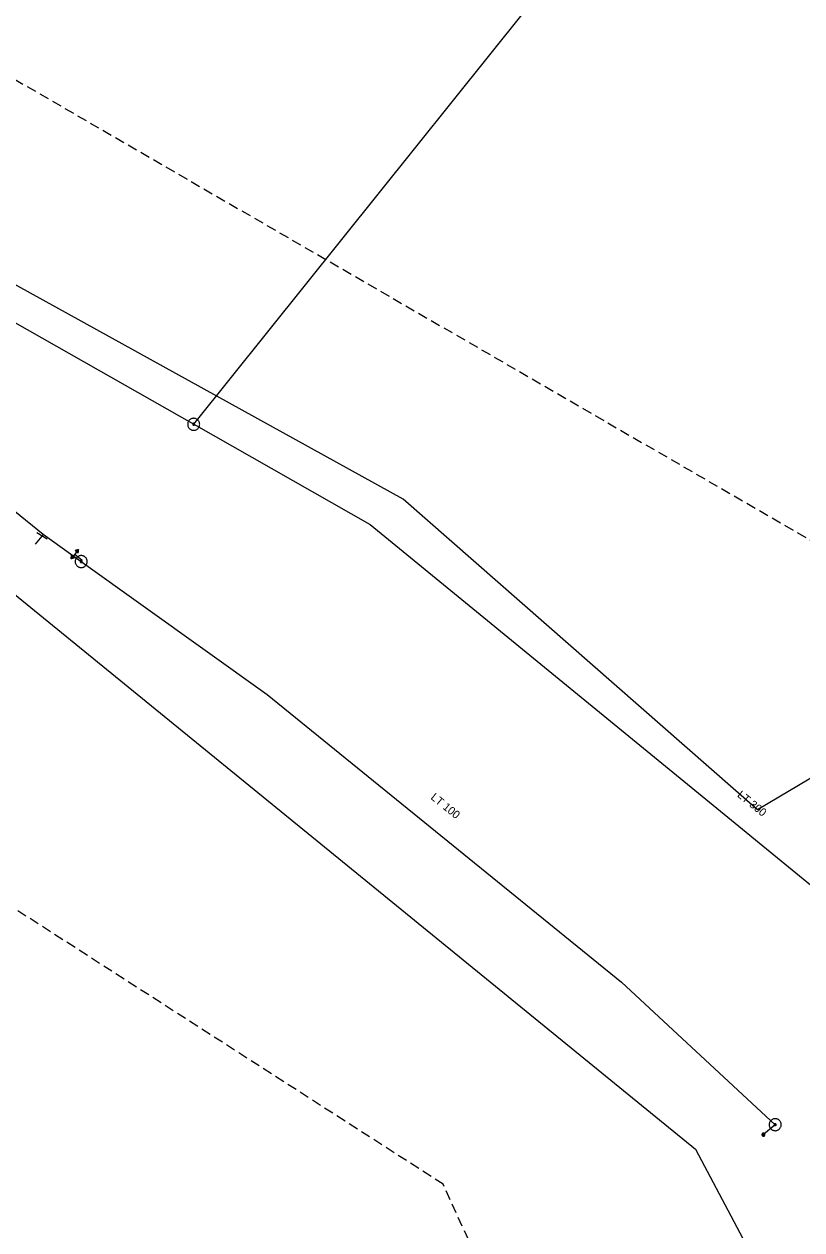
# Model space of a CAD drawing. Extents: x -687593 to -687108, y -975254 to -974717.
# Drawn here: x -687308.5 to -687243.7, y -975044.6 to -974944.2 of the extents above; entities that cross this region are included whole.
import ezdxf
from ezdxf.enums import TextEntityAlignment as Align

# ---------------------------------------------------------------- set-up
doc = ezdxf.new("R2010")
doc.units = 0
doc.header["$LTSCALE"] = 0.27
doc.linetypes.add('MEDIUM_DASHED', pattern=[4.5, 3, -1.5])
for name, color, linetype, lineweight in [('1', 7, 'Continuous', 25), ('13', 7, 'Continuous', 13), ('14', 7, 'Continuous', 13), ('17', 7, 'Continuous', 25), ('34', 7, 'Continuous', 13), ('47', 7, 'Continuous', 13), ('63', 7, 'MEDIUM_DASHED', 25), ('9', 7, 'Continuous', 13)]:
    doc.layers.add(name, color=color, linetype=linetype, lineweight=lineweight)

msp = doc.modelspace()

# ---------------------------------------------------------------- linework, layer by layer
at = {"layer": '1'}
msp.add_lwpolyline([(-687190.553, -975166.941), (-687164.86, -975177.861), (-687155.924, -975158.837), (-687125.348, -975155.541), (-687124.826, -975139.621), (-687173.065, -975131.89), (-687231.828, -975028.025), (-687222.959, -975015.464), (-687237.898, -975004.026), (-687247.4, -975009.654), (-687276.892, -974983.781), (-687453.606, -974886.044), (-687460.232, -974860.45), (-687474.874, -974858.564), (-687482.889, -974882.272), (-687502.421, -974882.802), (-687499.452, -974907.164), (-687464.42, -974904.824), (-687331.319, -974973.728), (-687252.566, -975037.916), (-687192.379, -975151.48)], close=True, dxfattribs=at)
at = {"layer": '13'}
msp.add_line((-687306.973, -974986.844), (-687307.541, -974987.516), dxfattribs=at)
at = {"layer": '14'}
for p, q in [((-687306.885, -974986.7), (-687306.973, -974986.844)), ((-687303.706, -974988.972), (-687303.618, -974988.865)), ((-687245.917, -975035.876), (-687246.898, -975036.705))]:
    msp.add_line(p, q, dxfattribs=at)
at = {"layer": '17'}
for points in [[(-687435.81, -974897.134), (-687294.34, -974977.541), (-687214.33, -974877.654)], [(-687358.699, -974951.407), (-687333.097, -974967.52), (-687321.645, -974974.737), (-687306.885, -974986.7), (-687303.706, -974988.972)], [(-687294.34, -974977.541), (-687279.655, -974985.888), (-687216.263, -975037.78), (-687194.919, -975091.897)], [(-687303.706, -974988.972), (-687288.215, -975000.045), (-687258.727, -975024.007), (-687245.917, -975035.876)]]:
    msp.add_lwpolyline(points, dxfattribs=at)
at = {"layer": '34'}
for p, q in [((-687306.546, -974987.104), (-687307.399, -974986.582)), ((-687304.176, -974988.053), (-687303.944, -974988.241)), ((-687304.147, -974988.042), (-687303.939, -974988.21)), ((-687304.117, -974988.036), (-687303.939, -974988.179)), ((-687304.089, -974988.026), (-687303.936, -974988.15)), ((-687304.062, -974988.019), (-687303.933, -974988.123)), ((-687304.033, -974988.007), (-687303.929, -974988.091)), ((-687304.006, -974987.999), (-687303.926, -974988.063)), ((-687303.976, -974987.993), (-687303.927, -974988.032)), ((-687303.946, -974987.98), (-687303.921, -974988)), ((-687304.264, -974988.654), (-687304.551, -974988.737)), ((-687304.548, -974988.709), (-687304.524, -974988.729)), ((-687304.541, -974988.647), (-687304.463, -974988.712)), ((-687304.541, -974988.677), (-687304.493, -974988.718)), ((-687304.538, -974988.619), (-687304.436, -974988.705)), ((-687304.532, -974988.588), (-687304.405, -974988.695)), ((-687304.53, -974988.56), (-687304.379, -974988.687)), ((-687304.526, -974988.5), (-687304.321, -974988.673)), ((-687304.525, -974988.531), (-687304.352, -974988.678)), ((-687304.52, -974988.469), (-687304.291, -974988.662)), ((-687304.235, -974988.355), (-687303.618, -974988.864))]:
    msp.add_line(p, q, dxfattribs=at)
for points in [[(-687303.946, -974988.269), (-687303.919, -974987.972), (-687304.551, -974988.737)], [(-687303.919, -974987.972), (-687304.204, -974988.061), (-687303.946, -974988.269)], [(-687304.551, -974988.737), (-687304.517, -974988.44), (-687304.264, -974988.654)]]:
    msp.add_lwpolyline(points, dxfattribs=at)
at = {"layer": '47'}
for points in [[(-687293.905, -974977.788), (-687293.882, -974977.741), (-687293.863, -974977.692), (-687293.85, -974977.641), (-687293.842, -974977.59), (-687293.84, -974977.537), (-687293.843, -974977.485), (-687293.852, -974977.433), (-687293.866, -974977.383), (-687293.884, -974977.335), (-687293.908, -974977.288), (-687293.937, -974977.243), (-687293.971, -974977.204), (-687294.007, -974977.167), (-687294.049, -974977.134), (-687294.092, -974977.106), (-687294.139, -974977.083), (-687294.188, -974977.064), (-687294.24, -974977.051), (-687294.29, -974977.043), (-687294.343, -974977.041), (-687294.395, -974977.044), (-687294.447, -974977.052), (-687294.498, -974977.066), (-687294.546, -974977.085), (-687294.592, -974977.109), (-687294.637, -974977.138), (-687294.677, -974977.171), (-687294.713, -974977.208), (-687294.746, -974977.25), (-687294.774, -974977.293), (-687294.797, -974977.34), (-687294.816, -974977.389), (-687294.83, -974977.44), (-687294.837, -974977.491), (-687294.839, -974977.544), (-687294.837, -974977.596), (-687294.828, -974977.648), (-687294.815, -974977.698), (-687294.795, -974977.747), (-687294.771, -974977.793), (-687294.742, -974977.838), (-687294.709, -974977.878), (-687294.672, -974977.914), (-687294.63, -974977.947), (-687294.587, -974977.975), (-687294.54, -974977.998), (-687294.491, -974978.017), (-687294.441, -974978.03), (-687294.389, -974978.038), (-687294.336, -974978.04), (-687294.284, -974978.038), (-687294.233, -974978.029), (-687294.182, -974978.015), (-687294.134, -974977.996), (-687294.087, -974977.972), (-687294.042, -974977.943), (-687294.003, -974977.91), (-687293.966, -974977.873), (-687293.933, -974977.831)], [(-687294.268, -974977.581), (-687294.264, -974977.573), (-687294.262, -974977.565), (-687294.259, -974977.557), (-687294.258, -974977.549), (-687294.258, -974977.54), (-687294.258, -974977.531), (-687294.259, -974977.523), (-687294.262, -974977.515), (-687294.265, -974977.507), (-687294.269, -974977.499), (-687294.274, -974977.492), (-687294.279, -974977.485), (-687294.285, -974977.479), (-687294.291, -974977.474), (-687294.299, -974977.469), (-687294.307, -974977.465), (-687294.315, -974977.463), (-687294.323, -974977.46), (-687294.331, -974977.459), (-687294.34, -974977.459), (-687294.349, -974977.459), (-687294.357, -974977.46), (-687294.365, -974977.463), (-687294.374, -974977.466), (-687294.381, -974977.47), (-687294.388, -974977.475), (-687294.395, -974977.48), (-687294.401, -974977.486), (-687294.406, -974977.492), (-687294.411, -974977.5), (-687294.415, -974977.508), (-687294.417, -974977.516), (-687294.42, -974977.524), (-687294.421, -974977.532), (-687294.421, -974977.541), (-687294.421, -974977.549), (-687294.42, -974977.558), (-687294.417, -974977.566), (-687294.414, -974977.575), (-687294.41, -974977.582), (-687294.405, -974977.589), (-687294.4, -974977.596), (-687294.394, -974977.602), (-687294.388, -974977.607), (-687294.38, -974977.612), (-687294.372, -974977.616), (-687294.364, -974977.618), (-687294.356, -974977.621), (-687294.348, -974977.622), (-687294.339, -974977.622), (-687294.331, -974977.622), (-687294.322, -974977.621), (-687294.314, -974977.618), (-687294.306, -974977.615), (-687294.298, -974977.611), (-687294.291, -974977.606), (-687294.284, -974977.601), (-687294.278, -974977.595), (-687294.273, -974977.589)], [(-687303.299, -974989.262), (-687303.271, -974989.218), (-687303.247, -974989.171), (-687303.23, -974989.122), (-687303.216, -974989.072), (-687303.208, -974989.02), (-687303.206, -974988.967), (-687303.209, -974988.916), (-687303.218, -974988.864), (-687303.231, -974988.814), (-687303.25, -974988.765), (-687303.275, -974988.718), (-687303.304, -974988.675), (-687303.337, -974988.634), (-687303.374, -974988.597), (-687303.415, -974988.565), (-687303.459, -974988.537), (-687303.506, -974988.513), (-687303.555, -974988.495), (-687303.605, -974988.482), (-687303.657, -974988.474), (-687303.71, -974988.472), (-687303.762, -974988.475), (-687303.814, -974988.483), (-687303.864, -974988.497), (-687303.912, -974988.516), (-687303.959, -974988.541), (-687304.003, -974988.569), (-687304.043, -974988.603), (-687304.08, -974988.64), (-687304.112, -974988.681), (-687304.14, -974988.725), (-687304.164, -974988.772), (-687304.183, -974988.821), (-687304.195, -974988.871), (-687304.203, -974988.923), (-687304.206, -974988.975), (-687304.203, -974989.028), (-687304.194, -974989.079), (-687304.18, -974989.13), (-687304.161, -974989.178), (-687304.136, -974989.225), (-687304.108, -974989.269), (-687304.074, -974989.309), (-687304.037, -974989.346), (-687303.996, -974989.378), (-687303.952, -974989.406), (-687303.905, -974989.43), (-687303.857, -974989.448), (-687303.806, -974989.461), (-687303.754, -974989.469), (-687303.702, -974989.472), (-687303.65, -974989.468), (-687303.598, -974989.46), (-687303.548, -974989.446), (-687303.499, -974989.427), (-687303.452, -974989.402), (-687303.409, -974989.374), (-687303.368, -974989.34), (-687303.331, -974989.303)], [(-687303.639, -974989.019), (-687303.634, -974989.012), (-687303.631, -974989.004), (-687303.628, -974988.997), (-687303.625, -974988.988), (-687303.624, -974988.979), (-687303.624, -974988.971), (-687303.624, -974988.962), (-687303.625, -974988.954), (-687303.628, -974988.946), (-687303.631, -974988.938), (-687303.635, -974988.93), (-687303.64, -974988.923), (-687303.645, -974988.916), (-687303.65, -974988.91), (-687303.658, -974988.905), (-687303.665, -974988.9), (-687303.673, -974988.897), (-687303.68, -974988.894), (-687303.689, -974988.891), (-687303.698, -974988.89), (-687303.706, -974988.89), (-687303.715, -974988.89), (-687303.723, -974988.891), (-687303.732, -974988.893), (-687303.739, -974988.897), (-687303.747, -974988.901), (-687303.754, -974988.906), (-687303.761, -974988.911), (-687303.767, -974988.916), (-687303.772, -974988.924), (-687303.777, -974988.931), (-687303.78, -974988.939), (-687303.783, -974988.946), (-687303.786, -974988.955), (-687303.787, -974988.964), (-687303.788, -974988.972), (-687303.787, -974988.981), (-687303.786, -974988.989), (-687303.784, -974988.998), (-687303.78, -974989.005), (-687303.776, -974989.013), (-687303.771, -974989.02), (-687303.766, -974989.027), (-687303.761, -974989.033), (-687303.753, -974989.038), (-687303.746, -974989.043), (-687303.738, -974989.046), (-687303.731, -974989.049), (-687303.722, -974989.052), (-687303.713, -974989.053), (-687303.705, -974989.054), (-687303.696, -974989.053), (-687303.688, -974989.052), (-687303.68, -974989.049), (-687303.672, -974989.046), (-687303.664, -974989.042), (-687303.657, -974989.037), (-687303.65, -974989.032), (-687303.644, -974989.027)], [(-687245.595, -975036.259), (-687245.557, -975036.223), (-687245.523, -975036.184), (-687245.493, -975036.141), (-687245.467, -975036.095), (-687245.447, -975036.047), (-687245.432, -975035.996), (-687245.422, -975035.945), (-687245.418, -975035.893), (-687245.418, -975035.841), (-687245.424, -975035.789), (-687245.436, -975035.738), (-687245.453, -975035.689), (-687245.475, -975035.641), (-687245.502, -975035.596), (-687245.533, -975035.554), (-687245.569, -975035.516), (-687245.608, -975035.482), (-687245.652, -975035.452), (-687245.697, -975035.426), (-687245.745, -975035.406), (-687245.796, -975035.391), (-687245.847, -975035.38), (-687245.899, -975035.376), (-687245.951, -975035.376), (-687246.003, -975035.383), (-687246.054, -975035.395), (-687246.104, -975035.412), (-687246.151, -975035.434), (-687246.196, -975035.461), (-687246.238, -975035.492), (-687246.276, -975035.528), (-687246.31, -975035.567), (-687246.341, -975035.61), (-687246.366, -975035.656), (-687246.386, -975035.704), (-687246.402, -975035.754), (-687246.412, -975035.805), (-687246.417, -975035.858), (-687246.416, -975035.91), (-687246.409, -975035.962), (-687246.397, -975036.013), (-687246.381, -975036.062), (-687246.358, -975036.11), (-687246.331, -975036.155), (-687246.3, -975036.197), (-687246.264, -975036.235), (-687246.225, -975036.269), (-687246.182, -975036.299), (-687246.136, -975036.325), (-687246.088, -975036.345), (-687246.038, -975036.361), (-687245.987, -975036.37), (-687245.935, -975036.375), (-687245.882, -975036.374), (-687245.83, -975036.368), (-687245.779, -975036.356), (-687245.73, -975036.339), (-687245.682, -975036.317), (-687245.637, -975036.29)], [(-687245.864, -975035.938), (-687245.857, -975035.933), (-687245.852, -975035.926), (-687245.847, -975035.919), (-687245.843, -975035.912), (-687245.839, -975035.904), (-687245.837, -975035.895), (-687245.835, -975035.887), (-687245.834, -975035.878), (-687245.835, -975035.87), (-687245.836, -975035.861), (-687245.838, -975035.853), (-687245.841, -975035.845), (-687245.844, -975035.837), (-687245.848, -975035.83), (-687245.854, -975035.823), (-687245.859, -975035.816), (-687245.866, -975035.811), (-687245.873, -975035.806), (-687245.88, -975035.802), (-687245.888, -975035.798), (-687245.897, -975035.796), (-687245.905, -975035.794), (-687245.914, -975035.793), (-687245.923, -975035.793), (-687245.931, -975035.795), (-687245.939, -975035.797), (-687245.947, -975035.8), (-687245.955, -975035.803), (-687245.962, -975035.807), (-687245.969, -975035.813), (-687245.976, -975035.818), (-687245.981, -975035.825), (-687245.986, -975035.832), (-687245.99, -975035.839), (-687245.994, -975035.847), (-687245.996, -975035.855), (-687245.998, -975035.864), (-687245.999, -975035.873), (-687245.999, -975035.882), (-687245.997, -975035.89), (-687245.995, -975035.898), (-687245.992, -975035.906), (-687245.989, -975035.914), (-687245.985, -975035.921), (-687245.979, -975035.928), (-687245.974, -975035.935), (-687245.967, -975035.94), (-687245.96, -975035.945), (-687245.953, -975035.949), (-687245.945, -975035.953), (-687245.937, -975035.955), (-687245.928, -975035.957), (-687245.919, -975035.958), (-687245.911, -975035.957), (-687245.902, -975035.956), (-687245.894, -975035.954), (-687245.886, -975035.951), (-687245.878, -975035.948), (-687245.871, -975035.944)]]:
    msp.add_lwpolyline(points, close=True, dxfattribs=at)
at = {"layer": '63'}
msp.add_lwpolyline([(-687526.998, -974914.677), (-687484.572, -974843.781), (-687484.572, -974843.781), (-687425.956, -974881.183), (-687425.956, -974881.183), (-687214.941, -975003.438), (-687214.941, -975003.438), (-687108.316, -975140.766), (-687108.316, -975140.766), (-687138.461, -975189.333), (-687138.461, -975189.333), (-687208.242, -975184.867), (-687208.242, -975184.867), (-687273.556, -975040.84), (-687273.556, -975040.84), (-687454.985, -974924.168), (-687454.985, -974924.168)], close=True, dxfattribs=at)
at = {"layer": '9'}
for points in [[(-687247.024, -975036.705), (-687247.024, -975036.718), (-687247.022, -975036.731), (-687247.019, -975036.744), (-687247.014, -975036.756), (-687247.008, -975036.768), (-687247.001, -975036.779), (-687246.993, -975036.789), (-687246.983, -975036.799), (-687246.973, -975036.807), (-687246.962, -975036.814), (-687246.95, -975036.82), (-687246.938, -975036.825), (-687246.925, -975036.828), (-687246.912, -975036.83), (-687246.899, -975036.832), (-687246.886, -975036.831), (-687246.873, -975036.829), (-687246.86, -975036.826), (-687246.848, -975036.821), (-687246.836, -975036.815), (-687246.825, -975036.808), (-687246.815, -975036.8), (-687246.805, -975036.79), (-687246.797, -975036.78), (-687246.79, -975036.769), (-687246.784, -975036.757), (-687246.779, -975036.745), (-687246.776, -975036.732), (-687246.774, -975036.719), (-687246.772, -975036.706), (-687246.773, -975036.693), (-687246.775, -975036.68), (-687246.778, -975036.667), (-687246.783, -975036.655), (-687246.789, -975036.643), (-687246.796, -975036.632), (-687246.804, -975036.622), (-687246.814, -975036.612), (-687246.824, -975036.604), (-687246.835, -975036.597), (-687246.847, -975036.591), (-687246.859, -975036.586), (-687246.872, -975036.583), (-687246.885, -975036.581), (-687246.898, -975036.58), (-687246.911, -975036.58), (-687246.924, -975036.582), (-687246.937, -975036.585), (-687246.949, -975036.59), (-687246.961, -975036.596), (-687246.972, -975036.603), (-687246.982, -975036.611), (-687246.992, -975036.621), (-687247, -975036.631), (-687247.007, -975036.642), (-687247.013, -975036.654), (-687247.018, -975036.666), (-687247.021, -975036.679), (-687247.023, -975036.692)], [(-687247.004, -975036.705), (-687247.005, -975036.716), (-687247.003, -975036.727), (-687247, -975036.738), (-687246.996, -975036.748), (-687246.991, -975036.758), (-687246.985, -975036.767), (-687246.978, -975036.776), (-687246.97, -975036.784), (-687246.961, -975036.791), (-687246.952, -975036.797), (-687246.942, -975036.802), (-687246.932, -975036.806), (-687246.921, -975036.809), (-687246.91, -975036.812), (-687246.899, -975036.812), (-687246.888, -975036.812), (-687246.877, -975036.81), (-687246.866, -975036.807), (-687246.856, -975036.803), (-687246.846, -975036.798), (-687246.837, -975036.792), (-687246.828, -975036.785), (-687246.82, -975036.777), (-687246.813, -975036.768), (-687246.807, -975036.759), (-687246.802, -975036.749), (-687246.798, -975036.739), (-687246.795, -975036.728), (-687246.793, -975036.717), (-687246.792, -975036.706), (-687246.792, -975036.695), (-687246.794, -975036.684), (-687246.797, -975036.673), (-687246.801, -975036.663), (-687246.806, -975036.653), (-687246.812, -975036.644), (-687246.819, -975036.635), (-687246.827, -975036.627), (-687246.836, -975036.62), (-687246.845, -975036.614), (-687246.855, -975036.609), (-687246.865, -975036.605), (-687246.876, -975036.602), (-687246.887, -975036.6), (-687246.898, -975036.6), (-687246.909, -975036.599), (-687246.92, -975036.601), (-687246.931, -975036.604), (-687246.941, -975036.608), (-687246.951, -975036.613), (-687246.96, -975036.619), (-687246.969, -975036.626), (-687246.977, -975036.634), (-687246.984, -975036.643), (-687246.99, -975036.652), (-687246.995, -975036.662), (-687246.999, -975036.672), (-687247.002, -975036.683), (-687247.004, -975036.694)], [(-687246.985, -975036.705), (-687246.985, -975036.714), (-687246.984, -975036.723), (-687246.981, -975036.732), (-687246.978, -975036.74), (-687246.974, -975036.748), (-687246.969, -975036.756), (-687246.963, -975036.763), (-687246.957, -975036.769), (-687246.95, -975036.775), (-687246.942, -975036.78), (-687246.934, -975036.784), (-687246.926, -975036.787), (-687246.917, -975036.79), (-687246.908, -975036.791), (-687246.899, -975036.793), (-687246.89, -975036.792), (-687246.881, -975036.791), (-687246.872, -975036.788), (-687246.864, -975036.785), (-687246.856, -975036.781), (-687246.848, -975036.776), (-687246.841, -975036.77), (-687246.835, -975036.764), (-687246.829, -975036.757), (-687246.824, -975036.749), (-687246.82, -975036.741), (-687246.817, -975036.733), (-687246.814, -975036.724), (-687246.813, -975036.715), (-687246.811, -975036.706), (-687246.812, -975036.697), (-687246.813, -975036.688), (-687246.816, -975036.679), (-687246.819, -975036.671), (-687246.823, -975036.663), (-687246.828, -975036.655), (-687246.834, -975036.648), (-687246.84, -975036.642), (-687246.847, -975036.636), (-687246.855, -975036.631), (-687246.863, -975036.627), (-687246.871, -975036.624), (-687246.88, -975036.621), (-687246.889, -975036.62), (-687246.898, -975036.619), (-687246.907, -975036.619), (-687246.916, -975036.62), (-687246.925, -975036.623), (-687246.933, -975036.626), (-687246.941, -975036.63), (-687246.949, -975036.635), (-687246.956, -975036.641), (-687246.962, -975036.647), (-687246.968, -975036.654), (-687246.973, -975036.662), (-687246.977, -975036.67), (-687246.98, -975036.678), (-687246.983, -975036.687), (-687246.984, -975036.696)], [(-687246.965, -975036.705), (-687246.965, -975036.712), (-687246.964, -975036.719), (-687246.963, -975036.726), (-687246.96, -975036.732), (-687246.957, -975036.738), (-687246.953, -975036.744), (-687246.949, -975036.75), (-687246.944, -975036.755), (-687246.938, -975036.759), (-687246.932, -975036.763), (-687246.926, -975036.766), (-687246.92, -975036.769), (-687246.913, -975036.77), (-687246.906, -975036.773), (-687246.899, -975036.773), (-687246.892, -975036.773), (-687246.885, -975036.771), (-687246.878, -975036.77), (-687246.872, -975036.767), (-687246.865, -975036.764), (-687246.86, -975036.76), (-687246.854, -975036.756), (-687246.849, -975036.751), (-687246.845, -975036.745), (-687246.841, -975036.739), (-687246.838, -975036.733), (-687246.835, -975036.727), (-687246.833, -975036.72), (-687246.832, -975036.713), (-687246.831, -975036.706), (-687246.831, -975036.699), (-687246.832, -975036.692), (-687246.834, -975036.685), (-687246.837, -975036.679), (-687246.84, -975036.672), (-687246.844, -975036.667), (-687246.848, -975036.661), (-687246.853, -975036.656), (-687246.859, -975036.652), (-687246.864, -975036.648), (-687246.871, -975036.645), (-687246.877, -975036.642), (-687246.884, -975036.64), (-687246.891, -975036.639), (-687246.898, -975036.639), (-687246.905, -975036.639), (-687246.912, -975036.639), (-687246.919, -975036.641), (-687246.925, -975036.644), (-687246.931, -975036.647), (-687246.937, -975036.651), (-687246.943, -975036.655), (-687246.948, -975036.66), (-687246.952, -975036.666), (-687246.956, -975036.671), (-687246.959, -975036.678), (-687246.962, -975036.684), (-687246.963, -975036.691), (-687246.965, -975036.698)], [(-687246.945, -975036.705), (-687246.945, -975036.71), (-687246.945, -975036.715), (-687246.944, -975036.72), (-687246.942, -975036.724), (-687246.94, -975036.729), (-687246.937, -975036.733), (-687246.934, -975036.736), (-687246.93, -975036.74), (-687246.927, -975036.743), (-687246.923, -975036.746), (-687246.918, -975036.748), (-687246.914, -975036.75), (-687246.909, -975036.751), (-687246.904, -975036.753), (-687246.899, -975036.753), (-687246.894, -975036.753), (-687246.889, -975036.752), (-687246.884, -975036.751), (-687246.88, -975036.749), (-687246.875, -975036.747), (-687246.871, -975036.744), (-687246.867, -975036.741), (-687246.864, -975036.737), (-687246.861, -975036.734), (-687246.858, -975036.73), (-687246.856, -975036.725), (-687246.854, -975036.721), (-687246.853, -975036.716), (-687246.852, -975036.711), (-687246.851, -975036.706), (-687246.851, -975036.701), (-687246.852, -975036.696), (-687246.853, -975036.691), (-687246.855, -975036.687), (-687246.857, -975036.682), (-687246.86, -975036.678), (-687246.863, -975036.674), (-687246.866, -975036.671), (-687246.87, -975036.668), (-687246.874, -975036.665), (-687246.879, -975036.663), (-687246.883, -975036.661), (-687246.888, -975036.66), (-687246.893, -975036.659), (-687246.898, -975036.659), (-687246.903, -975036.659), (-687246.908, -975036.66), (-687246.913, -975036.66), (-687246.917, -975036.662), (-687246.922, -975036.664), (-687246.926, -975036.667), (-687246.929, -975036.67), (-687246.933, -975036.673), (-687246.936, -975036.677), (-687246.939, -975036.681), (-687246.941, -975036.686), (-687246.943, -975036.69), (-687246.944, -975036.695), (-687246.945, -975036.7)], [(-687246.925, -975036.705), (-687246.925, -975036.708), (-687246.926, -975036.711), (-687246.925, -975036.713), (-687246.924, -975036.716), (-687246.923, -975036.719), (-687246.921, -975036.721), (-687246.919, -975036.723), (-687246.917, -975036.725), (-687246.915, -975036.727), (-687246.913, -975036.729), (-687246.91, -975036.731), (-687246.907, -975036.732), (-687246.905, -975036.732), (-687246.902, -975036.733), (-687246.899, -975036.733), (-687246.896, -975036.733), (-687246.893, -975036.733), (-687246.89, -975036.732), (-687246.888, -975036.731), (-687246.885, -975036.73), (-687246.883, -975036.728), (-687246.88, -975036.726), (-687246.878, -975036.724), (-687246.877, -975036.722), (-687246.875, -975036.72), (-687246.874, -975036.717), (-687246.872, -975036.714), (-687246.872, -975036.712), (-687246.871, -975036.709), (-687246.87, -975036.706), (-687246.871, -975036.703), (-687246.871, -975036.7), (-687246.872, -975036.697), (-687246.873, -975036.695), (-687246.874, -975036.692), (-687246.876, -975036.69), (-687246.877, -975036.687), (-687246.879, -975036.685), (-687246.882, -975036.684), (-687246.884, -975036.682), (-687246.887, -975036.681), (-687246.889, -975036.68), (-687246.892, -975036.679), (-687246.895, -975036.679), (-687246.898, -975036.678), (-687246.901, -975036.679), (-687246.904, -975036.678), (-687246.906, -975036.68), (-687246.909, -975036.68), (-687246.912, -975036.681), (-687246.914, -975036.683), (-687246.916, -975036.684), (-687246.918, -975036.686), (-687246.92, -975036.689), (-687246.922, -975036.691), (-687246.923, -975036.694), (-687246.924, -975036.696), (-687246.925, -975036.699), (-687246.925, -975036.702)], [(-687246.906, -975036.705), (-687246.906, -975036.707), (-687246.906, -975036.707), (-687246.905, -975036.707), (-687246.905, -975036.709), (-687246.906, -975036.71), (-687246.904, -975036.71), (-687246.904, -975036.71), (-687246.904, -975036.712), (-687246.904, -975036.712), (-687246.903, -975036.713), (-687246.901, -975036.713), (-687246.901, -975036.713), (-687246.901, -975036.714), (-687246.899, -975036.714), (-687246.899, -975036.714), (-687246.898, -975036.714), (-687246.897, -975036.714), (-687246.897, -975036.713), (-687246.896, -975036.713), (-687246.894, -975036.713), (-687246.894, -975036.712), (-687246.894, -975036.712), (-687246.893, -975036.711), (-687246.893, -975036.711), (-687246.891, -975036.71), (-687246.891, -975036.709), (-687246.89, -975036.708), (-687246.89, -975036.708), (-687246.89, -975036.707), (-687246.89, -975036.706), (-687246.89, -975036.705), (-687246.89, -975036.704), (-687246.89, -975036.704), (-687246.891, -975036.703), (-687246.891, -975036.702), (-687246.892, -975036.701), (-687246.892, -975036.701), (-687246.893, -975036.7), (-687246.893, -975036.7), (-687246.894, -975036.699), (-687246.895, -975036.699), (-687246.896, -975036.698), (-687246.896, -975036.698), (-687246.897, -975036.698), (-687246.898, -975036.698), (-687246.899, -975036.698), (-687246.9, -975036.698), (-687246.9, -975036.698), (-687246.901, -975036.699), (-687246.902, -975036.698), (-687246.903, -975036.7), (-687246.903, -975036.7), (-687246.904, -975036.7), (-687246.904, -975036.7), (-687246.905, -975036.702), (-687246.905, -975036.703), (-687246.905, -975036.704), (-687246.906, -975036.704), (-687246.906, -975036.705)]]:
    msp.add_lwpolyline(points, close=True, dxfattribs=at)

# ---------------------------------------------------------------- texts
at = {"layer": '1'}
for s, p in [('LT 100', (-687273.5798, -975009.5786)), ('LT 100', (-687273.5798, -975009.5786)), ('LT 100', (-687273.5798, -975009.5786)), ('LT 100', (-687273.5798, -975009.5786)), ('LT 100', (-687273.5798, -975009.5786)), ('LT 300', (-687248.0578, -975009.3776)), ('LT 300', (-687248.0578, -975009.3776)), ('LT 300', (-687248.0578, -975009.3776)), ('LT 300', (-687248.0578, -975009.3776)), ('LT 300', (-687248.0578, -975009.3776))]:
    msp.add_text(s, height=0.6667, rotation=321, dxfattribs=at).set_placement(p, align=Align.CENTER)

doc.saveas('drawing.dxf')
